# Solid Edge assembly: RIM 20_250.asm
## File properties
Title: Zylinder
Author: ahadarics
Template: iso metric assembly.asm
Last saved by: ahadarics
Revision: 16
Application: Solid Edge
Username: ahadarics
Dokumentum tartalom típus: 1
Document Number: RIM 20/250
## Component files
Kit_2.par
Profilrohr.par
Kolbenstange.par
Kit_1.par
Mutter_1.par
Mutter_2.par
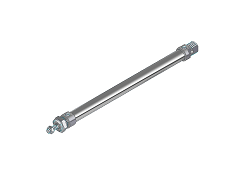
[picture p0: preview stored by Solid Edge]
